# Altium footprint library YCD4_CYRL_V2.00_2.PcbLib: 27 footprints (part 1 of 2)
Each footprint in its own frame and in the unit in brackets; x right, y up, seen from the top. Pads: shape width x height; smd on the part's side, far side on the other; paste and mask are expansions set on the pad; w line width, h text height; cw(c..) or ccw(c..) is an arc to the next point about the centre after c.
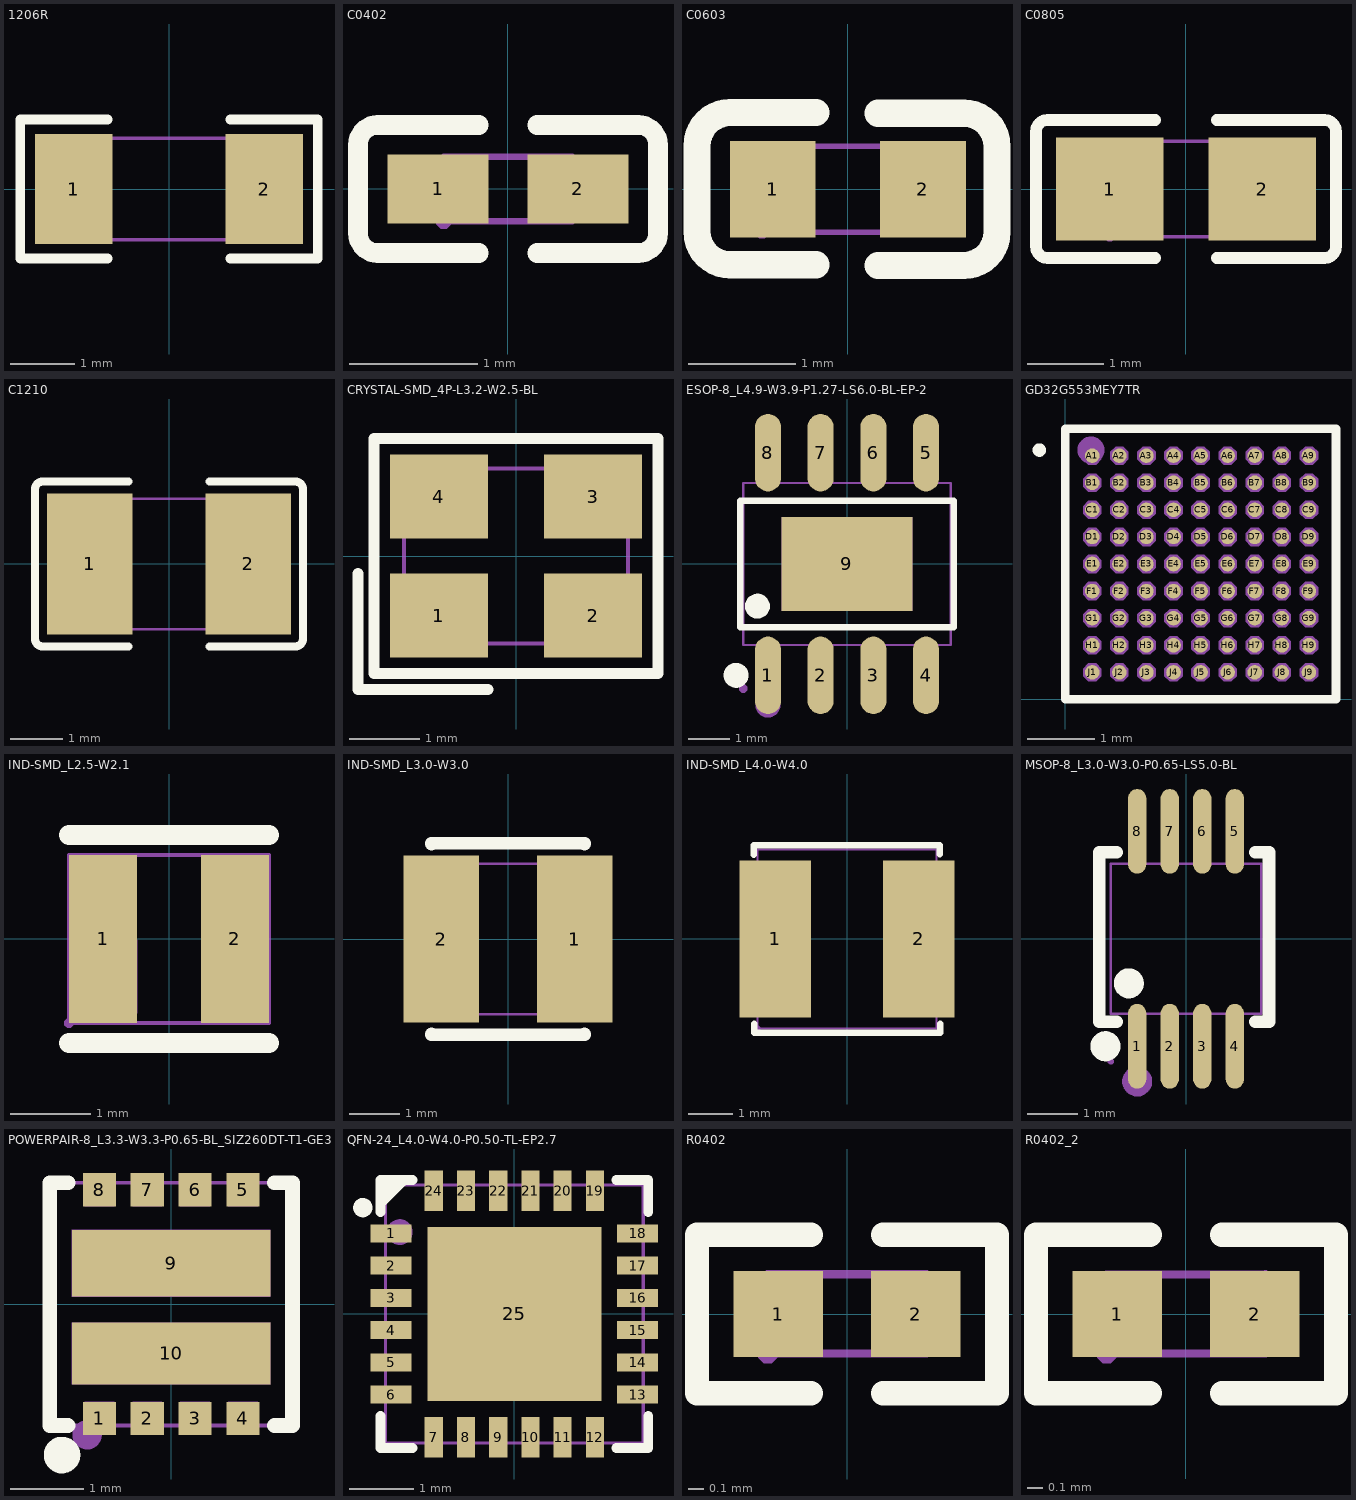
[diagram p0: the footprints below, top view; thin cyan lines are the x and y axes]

## 1206R [mm]
pads (2):
  rect 1.208x1.701 smd paste-100 mask+0.051: 1(-1.479,0) 2(1.479,0)
Top Overlay:
  lines w0.152: -0.951,-1.079 -2.311,-1.079 -2.311,1.079 -0.951,1.079 ; 0.951,-1.079 2.311,-1.079 2.311,1.079 0.951,1.079
Top Paste:
  region: -0.875,-0.75 -0.875,-0.389 -0.975,-0.289 -1.186,-0.289 -1.286,-0.189 -1.286,0.189 -1.186,0.289 -0.975,0.289 -0.875,0.389 -0.875,0.75 -0.975,0.85 -1.983,0.85 -2.083,0.75 -2.083,-0.75 -1.983,-0.85 -0.975,-0.85
  region: 0.875,-0.75 0.875,-0.389 0.975,-0.289 1.186,-0.289 1.286,-0.189 1.286,0.189 1.186,0.289 0.975,0.289 0.875,0.389 0.875,0.75 0.975,0.85 1.983,0.85 2.083,0.75 2.083,-0.75 1.983,-0.85 0.975,-0.85
Mechanical 15:
  region: 1.55,-0.788 1.55,0.788 1.1,0.788 1.1,-0.788
  region: -1.55,-0.788 -1.55,0.788 -1.1,0.788 -1.1,-0.788
  region: -1.49,-0.787 -1.49,-0.763 -1.525,-0.727 -1.575,-0.727 -1.61,-0.763 -1.61,-0.787 -1.61,-0.812 -1.575,-0.847 -1.525,-0.847 -1.49,-0.812 -1.49,-0.787
  lines w0.051: -1.55,-0.788 1.55,-0.788 1.55,0.788 -1.55,0.788 -1.55,-0.788
3D body: height 0.6, standoff 0, extent -1.479,-0.8 1.821,0.8

## C0402 [mm]
pads (2):
  rect 0.79x0.54 smd paste-100 mask+0.051: 1(-0.545,0) 2(0.545,0)
Top Overlay:
  lines w0.152: -0.226,-0.499 -1.016,-0.499 cw(c-1.016,-0.346) -1.169,-0.346 -1.169,0.346 cw(c-1.016,0.346) -1.016,0.499 -0.226,0.499 ; 0.226,-0.499 1.016,-0.499 ccw(c1.016,-0.346) 1.169,-0.346 1.169,0.346 ccw(c1.016,0.346) 1.016,0.499 0.226,0.499
Top Paste:
  region: -0.18,0.225 -0.18,-0.225 -0.25,-0.275 -0.73,-0.275 -0.78,-0.225 -0.78,0.225 -0.73,0.275 -0.25,0.275
  region: 0.78,0.225 0.78,-0.225 0.73,-0.275 0.25,-0.275 0.18,-0.225 0.18,0.225 0.25,0.275 0.73,0.275
Mechanical 15:
  region: -0.5,-0.25 -0.5,0.25 -0.25,0.25 -0.25,-0.25
  region: 0.5,-0.25 0.5,0.25 0.25,0.25 0.25,-0.25
  region: -0.44,-0.25 -0.44,-0.226 -0.475,-0.191 -0.524,-0.191 -0.559,-0.225 -0.56,-0.25 -0.559,-0.274 -0.525,-0.309 -0.476,-0.309 -0.441,-0.275 -0.44,-0.25
  lines w0.051: -0.5,-0.25 -0.5,0.25 0.5,0.25 0.5,-0.25 -0.5,-0.25
3D body: height 0.6, standoff 0, extent -0.731,-0.274 0.731,0.278

## C0603 [mm]
pads (2):
  rect 0.8x0.9 smd mask+0.102: 1(-0.7,0) 2(0.7,0)
Top Overlay:
  lines w0.254: -0.296,-0.704 -1.096,-0.704 cw(c-1.096,-0.394) -1.406,-0.394 -1.405,0.406 cw(c-1.096,0.406) -1.096,0.715 -0.296,0.715 ; 0.28,-0.71 1.08,-0.71 ccw(c1.08,-0.4) 1.39,-0.4 1.39,0.4 ccw(c1.08,0.4) 1.08,0.71 0.28,0.71
Mechanical 15:
  region: -0.8,-0.4 -0.8,0.4 -0.5,0.4 -0.5,-0.4
  region: 0.8,-0.4 0.8,0.4 0.5,0.4 0.5,-0.4
  region: -0.74,-0.4 -0.741,-0.376 -0.776,-0.343 -0.824,-0.343 -0.859,-0.376 -0.86,-0.4 -0.859,-0.424 -0.824,-0.458 -0.776,-0.458 -0.741,-0.424 -0.74,-0.4
  lines w0.051: -0.8,-0.4 -0.8,0.4 0.8,0.4 0.8,-0.4 -0.8,-0.4
3D body: height 1, standoff 0, extent -0.8,-0.4 1,0.4

## C0805 [mm]
pads (2):
  rect 1.41x1.35 smd paste-100 mask+0.051: 1(-1,0) 2(1,0)
Top Overlay:
  lines w0.152: -1.811,0.904 -0.401,0.904 ; -1.811,0.904 ccw(c-1.811,0.751) -1.964,0.751 -1.964,-0.751 ccw(c-1.811,-0.751) -1.811,-0.904 -0.401,-0.904 ; 0.401,-0.904 1.811,-0.904 ; 0.401,0.904 1.811,0.904 cw(c1.811,0.751) 1.964,0.751 ; 1.811,-0.904 ccw(c1.811,-0.751) 1.964,-0.751 1.964,0.751
Top Paste:
  region: 1.705,0.64 1.705,-0.64 1.655,-0.69 0.505,-0.69 0.455,-0.64 0.45,-0.23 0.9,-0.23 0.9,0.22 0.46,0.22 0.455,0.64 0.505,0.69 1.655,0.69
  region: -1.705,-0.64 -1.705,0.64 -1.655,0.69 -0.505,0.69 -0.455,0.64 -0.45,0.23 -0.9,0.23 -0.9,-0.22 -0.46,-0.22 -0.455,-0.64 -0.505,-0.69 -1.655,-0.69
Mechanical 15:
  region: 1,0.625 1,-0.625 0.5,-0.625 0.5,0.625
  region: -1,-0.625 -1,0.625 -0.5,0.625 -0.5,-0.625
  region: -0.94,-0.625 -0.94,-0.6 -0.975,-0.565 -1.025,-0.565 -1.06,-0.6 -1.06,-0.625 -1.06,-0.65 -1.025,-0.685 -0.975,-0.685 -0.94,-0.65 -0.94,-0.625
  lines w0.051: -1,-0.625 1,-0.625 1,0.625 -1,0.625 -1,-0.625
3D body: height 1.4, standoff 0, extent -1.097,-0.625 1.103,0.625

## C1210 [mm]
pads (2):
  rect 1.635x2.7 smd paste-100 mask+0.051: 1(-1.517,0) 2(1.517,0)
Top Overlay:
  lines w0.152: -0.776,-1.579 -2.411,-1.579 cw(c-2.411,-1.426) -2.564,-1.426 -2.564,1.426 cw(c-2.411,1.426) -2.411,1.579 -0.776,1.579 ; 0.776,-1.579 2.411,-1.579 ccw(c2.411,-1.426) 2.564,-1.426 2.564,1.426 ccw(c2.411,1.426) 2.411,1.579 0.776,1.579
Top Paste:
  region: 0.7,-1.25 0.7,-0.559 0.8,-0.459 1.156,-0.459 1.256,-0.359 1.256,0.359 1.156,0.459 0.8,0.459 0.7,0.559 0.7,1.25 0.8,1.35 2.235,1.35 2.335,1.25 2.335,-1.25 2.235,-1.35 0.8,-1.35
  region: -0.7,-1.25 -0.7,-0.559 -0.8,-0.459 -1.156,-0.459 -1.256,-0.359 -1.256,0.359 -1.156,0.459 -0.8,0.459 -0.7,0.559 -0.7,1.25 -0.8,1.35 -2.235,1.35 -2.335,1.25 -2.335,-1.25 -2.235,-1.35 -0.8,-1.35
Mechanical 15:
  region: -1.54,-1.25 -1.541,-1.226 -1.576,-1.193 -1.624,-1.193 -1.659,-1.226 -1.66,-1.25 -1.659,-1.274 -1.624,-1.307 -1.576,-1.307 -1.541,-1.274 -1.54,-1.25
  region: -1.6,-1.25 -1.6,1.25 -1,1.25 -1,-1.25
  region: 1.6,-1.25 1.6,1.25 1,1.25 1,-1.25
  lines w0.051: -1.6,-1.25 -1.6,1.25 1.6,1.25 1.6,-1.25 -1.6,-1.25
3D body: height 2.8, standoff 0, extent -1.403,-1.25 1.797,1.25

## CRYSTAL-SMD_4P-L3.2-W2.5-BL [mm]
pads (4):
  rect 1.4x1.2 smd: 1(-1.1,-0.85) 2(1.1,-0.85) 3(1.1,0.85) 4(-1.1,0.85)
Top Overlay:
  lines w0.152: -2.257,-0.25 -2.257,-1.907 -0.4,-1.907 ; -2.029,-1.678 -2.029,1.679 2.029,1.679 2.029,-1.678 -2.029,-1.678
Mechanical 6:
  circle w0.36: c-1.143,-0.889 r0.18
Mechanical 15:
  region: -1.54,-1.25 -1.54,-1.225 -1.575,-1.19 -1.625,-1.19 -1.66,-1.225 -1.66,-1.25 -1.66,-1.275 -1.625,-1.31 -1.575,-1.31 -1.54,-1.275 -1.54,-1.25
  region: -1.5,1.15 -0.6,1.15 -0.6,0.35 -1.5,0.35
  region: 0.6,1.15 1.5,1.15 1.5,0.35 0.6,0.35
  region: 0.6,-0.35 1.5,-0.35 1.5,-1.15 0.6,-1.15
  region: -1.5,-0.35 -0.6,-0.35 -0.6,-1.15 -1.5,-1.15
  lines w0.051: -1.6,-1.25 -1.6,1.25 1.6,1.25 1.6,-1.25 -1.6,-1.25
3D body: height 0.8, standoff 0, extent -1.6,-1.25 1.6,1.25

## ESOP-8_L4.9-W3.9-P1.27-LS6.0-BL-EP-2 [mm]
pads (9):
  oval 0.63x1.865 smd: 1(-1.905,-2.683) 2(-0.635,-2.683) 3(0.635,-2.683) 4(1.905,-2.683) 5(1.905,2.682) 6(0.635,2.682) 7(-0.635,2.682) 8(-1.905,2.682)
  rect 3.15x2.26 smd paste+0 mask+0.05: 9(0,0)
Top Overlay:
  circle w0.3: c-2.672,-2.683 r0.15
  circle w0.3: c-2.159,-1.016 r0.15
  lines w0.152: -2.576,-1.521 2.576,-1.521 2.576,1.521 -2.576,1.521 -2.576,-1.521
Mechanical 6:
  circle w0.3: c-1.905,-3.4 r0.15
Mechanical 15:
  region: -1.575,1.13 1.575,1.13 1.575,-1.13 -1.575,-1.13
  region: -2.115,-3 -2.115,-2.165 -1.695,-2.165 -1.695,-3
  region: -2.115,-2.175 -2.115,-1.94 -1.695,-1.94 -1.695,-2.175
  region: -0.845,-3 -0.845,-2.165 -0.425,-2.165 -0.425,-3
  region: -0.845,-2.175 -0.845,-1.94 -0.425,-1.94 -0.425,-2.175
  region: 0.425,-3 0.425,-2.165 0.845,-2.165 0.845,-3
  region: 0.425,-2.175 0.425,-1.94 0.845,-1.94 0.845,-2.175
  region: 1.695,-3 1.695,-2.165 2.115,-2.165 2.115,-3
  region: 1.695,-2.175 1.695,-1.94 2.115,-1.94 2.115,-2.175
  region: -2.115,2.165 -2.115,3 -1.695,3 -1.695,2.165
  region: -2.115,1.94 -2.115,2.175 -1.695,2.175 -1.695,1.94
  region: -0.845,2.165 -0.845,3 -0.425,3 -0.425,2.165
  region: -0.845,1.94 -0.845,2.175 -0.425,2.175 -0.425,1.94
  region: 0.425,2.165 0.425,3 0.845,3 0.845,2.165
  region: 0.425,1.94 0.425,2.175 0.845,2.175 0.845,1.94
  region: 1.695,2.165 1.695,3 2.115,3 2.115,2.165
  region: 1.695,1.94 1.695,2.175 2.115,2.175 2.115,1.94
  region: -2.4,-3 -2.4,-2.959 -2.459,-2.9 -2.541,-2.9 -2.6,-2.959 -2.6,-3 -2.6,-3.042 -2.541,-3.1 -2.458,-3.1 -2.4,-3.041 -2.4,-3
  lines w0.051: -2.5,-1.95 2.5,-1.95 2.5,1.95 -2.5,1.95 -2.5,-1.95
3D body: height 1.7, standoff 0, extent -2.505,-1.943 2.489,1.943

## GD32G553MEY7TR [mm]
pads (81):
  round 0.216 smd paste-100 mask+0.051: A1(0.4,3.6) A2(0.8,3.6) A3(1.2,3.6) A4(1.6,3.6) A5(2,3.6) A6(2.4,3.6) A7(2.8,3.6) A8(3.2,3.6) A9(3.6,3.6) B1(0.4,3.2) B2(0.8,3.2) B3(1.2,3.2) B4(1.6,3.2) B5(2,3.2) B6(2.4,3.2) B7(2.8,3.2) B8(3.2,3.2) B9(3.6,3.2) C1(0.4,2.8) C2(0.8,2.8) C3(1.2,2.8) C4(1.6,2.8) C5(2,2.8) C6(2.4,2.8) C7(2.8,2.8) C8(3.2,2.8) C9(3.6,2.8) D1(0.4,2.4) D2(0.8,2.4) D3(1.2,2.4) D4(1.6,2.4) D5(2,2.4) D6(2.4,2.4) D7(2.8,2.4) D8(3.2,2.4) D9(3.6,2.4) E1(0.4,2) E2(0.8,2) E3(1.2,2) E4(1.6,2) E5(2,2) E6(2.4,2) E7(2.8,2) E8(3.2,2) E9(3.6,2) F1(0.4,1.6) F2(0.8,1.6) F3(1.2,1.6) F4(1.6,1.6) F5(2,1.6) F6(2.4,1.6) F7(2.8,1.6) F8(3.2,1.6) F9(3.6,1.6) G1(0.4,1.2) G2(0.8,1.2) G3(1.2,1.2) G4(1.6,1.2) G5(2,1.2) G6(2.4,1.2) G7(2.8,1.2) G8(3.2,1.2) G9(3.6,1.2) H1(0.4,0.8) H2(0.8,0.8) H3(1.2,0.8) H4(1.6,0.8) H5(2,0.8) H6(2.4,0.8) H7(2.8,0.8) H8(3.2,0.8) H9(3.6,0.8) J1(0.4,0.4) J2(0.8,0.4) J3(1.2,0.4) J4(1.6,0.4) J5(2,0.4) J6(2.4,0.4) J7(2.8,0.4) J8(3.2,0.4) J9(3.6,0.4)
Top Overlay:
  circle w0.1: c-0.381,3.683 r0.05
  lines w0.127: 0,0 0,4 4,4 4,0 0,0
Top Paste:
  drawing of 81 lines, arcs and shapes, not listed
Mechanical 6:
  circle w0.2: c0.381,3.683 r0.1
Mechanical 15:
  drawing of 81 lines, arcs and shapes, not listed

## IND-SMD_L2.5-W2.1 [mm]
pads (2):
  rect 0.85x2.1 smd: 1(-0.825,0) 2(0.825,0)
Top Overlay:
  lines w0.254: -1.25,-1.3 1.25,-1.3 ; -1.25,1.3 1.25,1.3
Mechanical 15:
  region: 1.25,0.925 1.25,-0.925 0.4,-0.925 0.4,0.925
  region: -0.4,0.925 -0.4,-0.925 -1.25,-0.925 -1.25,0.925
  region: -1.19,-1.05 -1.19,-1.025 -1.225,-0.99 -1.275,-0.99 -1.31,-1.025 -1.31,-1.05 -1.31,-1.075 -1.275,-1.11 -1.225,-1.11 -1.19,-1.075 -1.19,-1.05
  lines w0.051: -1.25,-1.05 1.25,-1.05 1.25,1.05 -1.25,1.05 -1.25,-1.05
3D body: height 1.25, standoff 0, extent -1.25,-1.05 1.25,1.05

## IND-SMD_L3.0-W3.0 [mm]
pads (2):
  rect 1.5x3.32 smd: 1(1.328,0) 2(-1.328,0)
Top Overlay:
  lines w0.254: -1.524,-1.891 -1.524,-1.905 1.524,-1.905 1.524,-1.891 ; -1.524,1.891 -1.524,1.905 1.524,1.905 1.524,1.891
Mechanical 15:
  region: -1.5,-1.45 -1.5,1.45 -0.75,1.45 -0.75,-1.45
  region: 1.5,-1.45 1.5,1.45 0.75,1.45 0.75,-1.45
  region: -1.44,-1.5 -1.44,-1.475 -1.475,-1.44 -1.525,-1.44 -1.56,-1.475 -1.56,-1.5 -1.56,-1.525 -1.525,-1.56 -1.475,-1.56 -1.44,-1.525 -1.44,-1.5
  lines w0.051: -1.5,-1.5 -1.5,1.5 1.5,1.5 1.5,-1.5 -1.5,-1.5
3D body: height 1.5, standoff 0, extent -1.5,-1.5 1.5,1.5

## IND-SMD_L4.0-W4.0 [mm]
pads (2):
  rect 1.6x3.5 smd: 1(-1.6,0) 2(1.6,0)
Top Overlay:
  lines w0.15: -2.08,1.88 -2.083,2.095 2.07,2.095 2.07,1.9 ; -2.07,-1.89 -2.07,-2.096 2.082,-2.096 2.08,-1.9
Mechanical 15:
  region: -2,1.65 -1.05,1.65 -1.05,-1.65 -2,-1.65
  region: 1.05,1.65 2,1.65 2,-1.65 1.05,-1.65
  region: -1.94,-2 -1.941,-1.976 -1.976,-1.943 -2.024,-1.943 -2.059,-1.976 -2.06,-2 -2.059,-2.024 -2.024,-2.057 -1.976,-2.057 -1.941,-2.024
  lines w0.051: -2,-2 2,-2 2,2 -2,2 -2,-2
3D body: height 1.8, standoff 0, extent -2,-2 2,2

## MSOP-8_L3.0-W3.0-P0.65-LS5.0-BL [mm]
pads (8):
  oval 0.364x1.692 smd: 1(-0.975,-2.146) 2(-0.325,-2.146) 3(0.325,-2.146) 4(0.975,-2.146) 5(0.975,2.146) 6(0.325,2.146) 7(-0.325,2.146) 8(-0.975,2.146)
Top Overlay:
  circle w0.3: c-1.609,-2.146 r0.15
  circle w0.3: c-1.143,-0.889 r0.15
  lines w0.254: -1.73,1.724 -1.73,-1.652 -1.723,-1.658 -1.388,-1.658 ; -1.717,1.71 -1.697,1.73 -1.388,1.73 ; 1.388,-1.658 1.659,-1.658 1.659,1.73 1.388,1.73
Mechanical 6:
  circle w0.3: c-0.975,-2.85 r0.15
Mechanical 15:
  region: 0.82,1.86 0.82,1.49 1.13,1.49 1.13,1.86
  region: 0.82,2.45 0.82,1.85 1.13,1.85 1.13,2.45
  region: 0.17,1.86 0.17,1.49 0.48,1.49 0.48,1.86
  region: 0.17,2.45 0.17,1.85 0.48,1.85 0.48,2.45
  region: -0.48,1.86 -0.48,1.49 -0.17,1.49 -0.17,1.86
  region: -0.48,2.45 -0.48,1.85 -0.17,1.85 -0.17,2.45
  region: -1.13,1.86 -1.13,1.49 -0.82,1.49 -0.82,1.86
  region: -1.13,2.45 -1.13,1.85 -0.82,1.85 -0.82,2.45
  region: 0.82,-1.86 0.82,-1.49 1.13,-1.49 1.13,-1.86
  region: 0.82,-2.45 0.82,-1.85 1.13,-1.85 1.13,-2.45
  region: 0.17,-1.86 0.17,-1.49 0.48,-1.49 0.48,-1.86
  region: 0.17,-2.45 0.17,-1.85 0.48,-1.85 0.48,-2.45
  region: -0.48,-1.86 -0.48,-1.49 -0.17,-1.49 -0.17,-1.86
  region: -0.48,-2.45 -0.48,-1.85 -0.17,-1.85 -0.17,-2.45
  region: -1.13,-1.86 -1.13,-1.49 -0.82,-1.49 -0.82,-1.86
  region: -1.13,-2.45 -1.13,-1.85 -0.82,-1.85 -0.82,-2.45
  region: -1.44,-2.45 -1.44,-2.425 -1.475,-2.39 -1.525,-2.39 -1.56,-2.425 -1.56,-2.45 -1.56,-2.475 -1.525,-2.51 -1.475,-2.51 -1.44,-2.475 -1.44,-2.45
  lines w0.051: -1.5,-1.5 1.5,-1.5 1.5,1.5 -1.5,1.5 -1.5,-1.5
3D body: height 1.7, standoff 0, extent -1.524,-1.524 1.524,1.524

## POWERPAIR-8_L3.3-W3.3-P0.65-BL_SIZ260DT-T1-GE3 [mm]
pads (10):
  rect 0.45x0.45 smd paste+0 mask+0.05: 1(-0.975,-1.555) 2(-0.325,-1.555) 3(0.325,-1.555) 4(0.975,-1.555) 5(0.975,1.555) 6(0.325,1.555) 7(-0.325,1.555) 8(-0.975,1.555)
  rect 2.7x0.91 smd paste+0 mask+0.05: 9(0,0.555)
  rect 2.7x0.84 smd paste+0 mask+0.05: 10(0,-0.671)
Top Overlay:
  circle w0.254: c-1.485,-2.053 r0.122
  lines w0.2: -1.404,-1.651 -1.651,-1.651 -1.651,1.651 -1.404,1.651 ; 1.404,-1.651 1.651,-1.651 1.651,1.651 1.404,1.651
Mechanical 6:
  circle w0.2: c-1.143,-1.778 r0.1
Mechanical 15:
  region: -1.59,-1.65 -1.591,-1.626 -1.626,-1.593 -1.674,-1.593 -1.709,-1.626 -1.71,-1.65 -1.709,-1.674 -1.674,-1.707 -1.626,-1.707 -1.591,-1.674 -1.59,-1.65
  region: -1.175,1.65 -0.775,1.65 -0.775,1.33 -1.175,1.33
  region: -0.525,1.65 -0.125,1.65 -0.125,1.33 -0.525,1.33
  region: 0.125,1.65 0.525,1.65 0.525,1.33 0.125,1.33
  region: 0.775,1.65 1.175,1.65 1.175,1.33 0.775,1.33
  region: 0.775,-1.33 1.175,-1.33 1.175,-1.65 0.775,-1.65
  region: 0.125,-1.33 0.525,-1.33 0.525,-1.65 0.125,-1.65
  region: -0.525,-1.33 -0.125,-1.33 -0.125,-1.65 -0.525,-1.65
  region: -1.175,-1.33 -0.775,-1.33 -0.775,-1.65 -1.175,-1.65
  region: -1.35,1.01 1.35,1.01 1.35,0.1 -1.35,0.1
  region: -1.35,-0.251 1.35,-0.251 1.35,-1.091 -1.35,-1.091
  lines w0.051: -1.65,-1.65 -1.65,1.65 1.65,1.65 1.65,-1.65 -1.65,-1.65
3D body: height 0.8, standoff 0, extent -1.651,-1.651 1.651,1.651

## QFN-24_L4.0-W4.0-P0.50-TL-EP2.7 [mm]
pads (25):
  rect 0.633x0.28 smd paste-100 mask+0.051: 1(-1.912,1.25) 2(-1.912,0.75) 3(-1.912,0.25) 4(-1.912,-0.25) 5(-1.912,-0.75) 6(-1.912,-1.25) 13(1.912,-1.25) 14(1.912,-0.75) 15(1.912,-0.25) 16(1.912,0.25) 17(1.912,0.75) 18(1.912,1.25)
  rect 0.28x0.633 smd paste-100 mask+0.051: 7(-1.25,-1.912) 8(-0.75,-1.912) 9(-0.25,-1.912) 10(0.25,-1.912) 11(0.75,-1.912) 12(1.25,-1.912) 19(1.25,1.912) 20(0.75,1.912) 21(0.25,1.912) 22(-0.25,1.912) 23(-0.75,1.912) 24(-1.25,1.912)
  rect 2.7x2.7 smd paste-100 mask+0.051: 25(0,0)
Top Overlay:
  circle w0.15: c-2.35,1.65 r0.075
  region: -1.58,2.076 -2.076,2.076 -2.076,1.7
  lines w0.152: -2.076,-1.58 -2.076,-2.076 -1.58,-2.076 ; -2.076,1.58 -2.076,2.076 -1.58,2.076 -1.713,2.076 -2.076,1.713 ; 1.58,-2.076 2.076,-2.076 2.076,-1.58 ; 1.58,2.076 2.076,2.076 2.076,1.58
Top Paste:
  region: -1.08,1.08 1.08,1.08 1.08,-1.08 -1.08,-1.08
  region: -2.228,1.39 -1.595,1.39 -1.595,1.11 -2.228,1.11
  region: -2.228,0.89 -1.595,0.89 -1.595,0.61 -2.228,0.61
  region: -2.228,0.39 -1.595,0.39 -1.595,0.11 -2.228,0.11
  region: -2.228,-0.11 -1.595,-0.11 -1.595,-0.39 -2.228,-0.39
  region: -2.228,-0.61 -1.595,-0.61 -1.595,-0.89 -2.228,-0.89
  region: -2.228,-1.11 -1.595,-1.11 -1.595,-1.39 -2.228,-1.39
  region: -1.39,-1.595 -1.11,-1.595 -1.11,-2.228 -1.39,-2.228
  region: -0.89,-1.595 -0.61,-1.595 -0.61,-2.228 -0.89,-2.228
  region: -0.39,-1.595 -0.11,-1.595 -0.11,-2.228 -0.39,-2.228
  region: 0.11,-1.595 0.39,-1.595 0.39,-2.228 0.11,-2.228
  region: 0.61,-1.595 0.89,-1.595 0.89,-2.228 0.61,-2.228
  region: 1.11,-1.595 1.39,-1.595 1.39,-2.228 1.11,-2.228
  region: 1.595,-1.11 2.228,-1.11 2.228,-1.39 1.595,-1.39
  region: 1.595,-0.61 2.228,-0.61 2.228,-0.89 1.595,-0.89
  region: 1.595,-0.11 2.228,-0.11 2.228,-0.39 1.595,-0.39
  region: 1.595,0.39 2.228,0.39 2.228,0.11 1.595,0.11
  region: 1.595,0.89 2.228,0.89 2.228,0.61 1.595,0.61
  region: 1.595,1.39 2.228,1.39 2.228,1.11 1.595,1.11
  region: 1.11,2.228 1.39,2.228 1.39,1.595 1.11,1.595
  region: 0.61,2.228 0.89,2.228 0.89,1.595 0.61,1.595
  region: 0.11,2.228 0.39,2.228 0.39,1.595 0.11,1.595
  region: -0.39,2.228 -0.11,2.228 -0.11,1.595 -0.39,1.595
  region: -0.89,2.228 -0.61,2.228 -0.61,1.595 -0.89,1.595
  region: -1.39,2.228 -1.11,2.228 -1.11,1.595 -1.39,1.595
Mechanical 6:
  circle w0.2: c-1.778,1.27 r0.1
Mechanical 15:
  region: -1.94,2 -1.941,2.024 -1.976,2.059 -2.024,2.059 -2.059,2.024 -2.06,2 -2.059,1.975 -2.024,1.941 -1.975,1.941 -1.941,1.976 -1.94,2
  region: -2,1.37 -1.62,1.37 -1.62,1.13 -2,1.13
  region: -2,0.87 -1.62,0.87 -1.62,0.63 -2,0.63
  region: -2,0.37 -1.62,0.37 -1.62,0.13 -2,0.13
  region: -2,-0.13 -1.62,-0.13 -1.62,-0.37 -2,-0.37
  region: -2,-0.63 -1.62,-0.63 -1.62,-0.87 -2,-0.87
  region: -2,-1.13 -1.62,-1.13 -1.62,-1.37 -2,-1.37
  region: -1.37,-1.62 -1.13,-1.62 -1.13,-2 -1.37,-2
  region: -0.87,-1.62 -0.63,-1.62 -0.63,-2 -0.87,-2
  region: -0.37,-1.62 -0.13,-1.62 -0.13,-2 -0.37,-2
  region: 0.13,-1.62 0.37,-1.62 0.37,-2 0.13,-2
  region: 0.63,-1.62 0.87,-1.62 0.87,-2 0.63,-2
  region: 1.13,-1.62 1.37,-1.62 1.37,-2 1.13,-2
  region: 2,-1.13 1.62,-1.13 1.62,-1.37 2,-1.37
  region: 2,-0.63 1.62,-0.63 1.62,-0.87 2,-0.87
  region: 2,-0.13 1.62,-0.13 1.62,-0.37 2,-0.37
  region: 2,0.37 1.62,0.37 1.62,0.13 2,0.13
  region: 2,0.87 1.62,0.87 1.62,0.63 2,0.63
  region: 2,1.37 1.62,1.37 1.62,1.13 2,1.13
  region: 1.13,1.62 1.37,1.62 1.37,2 1.13,2
  region: 0.63,1.62 0.87,1.62 0.87,2 0.63,2
  region: 0.13,1.62 0.37,1.62 0.37,2 0.13,2
  region: -0.37,1.62 -0.13,1.62 -0.13,2 -0.37,2
  region: -0.87,1.62 -0.63,1.62 -0.63,2 -0.87,2
  region: -1.37,1.62 -1.13,1.62 -1.13,2 -1.37,2
  region: -1,1.25 1.25,1.25 1.25,-1.25 -1.25,-1.25 -1.25,1
  lines w0.051: -2,-2 2,-2 2,2 -2,2 -2,-2
3D body: height 0.9, standoff 0, extent -2.007,-2.018 2.032,2.039

## R0402 [mm]
pads (2):
  rect 0.566x0.54 smd paste-100 mask+0.051: 1(-0.433,0) 2(0.433,0)
Top Overlay:
  lines w0.152: -0.226,-0.499 -0.944,-0.499 -0.944,0.499 -0.226,0.499 ; 0.226,-0.499 0.944,-0.499 0.944,0.499 0.226,0.499
Top Paste:
  region: 0.135,-0.23 0.135,0.23 0.175,0.27 0.676,0.27 0.716,0.23 0.716,-0.23 0.676,-0.27 0.175,-0.27
  region: -0.135,-0.23 -0.135,0.23 -0.175,0.27 -0.676,0.27 -0.716,0.23 -0.716,-0.23 -0.676,-0.27 -0.175,-0.27
Mechanical 15:
  region: 0.251,-0.25 0.251,0.25 0.501,0.25 0.501,-0.25
  region: -0.249,0.25 -0.249,-0.25 -0.499,-0.25 -0.499,0.25
  region: -0.44,-0.25 -0.44,-0.225 -0.475,-0.19 -0.525,-0.19 -0.56,-0.225 -0.56,-0.25 -0.56,-0.275 -0.525,-0.31 -0.475,-0.31 -0.44,-0.275 -0.44,-0.25
  lines w0.051: -0.5,-0.25 -0.5,0.25 0.5,0.25 0.5,-0.25 -0.5,-0.25
3D body: height 0.6, standoff 0, extent -0.5,-0.25 0.501,0.25

## R0402_2 [mm]
pads (2):
  rect 0.566x0.54 smd paste-100 mask+0.051: 1(-0.433,0) 2(0.433,0)
Top Overlay:
  lines w0.152: -0.226,-0.499 -0.944,-0.499 -0.944,0.499 -0.226,0.499 ; 0.226,-0.499 0.944,-0.499 0.944,0.499 0.226,0.499
Top Paste:
  region: 0.135,-0.23 0.135,0.23 0.175,0.27 0.676,0.27 0.716,0.23 0.716,-0.23 0.676,-0.27 0.175,-0.27
  region: -0.135,-0.23 -0.135,0.23 -0.175,0.27 -0.676,0.27 -0.716,0.23 -0.716,-0.23 -0.676,-0.27 -0.175,-0.27
Mechanical 15:
  region: 0.251,-0.25 0.251,0.25 0.501,0.25 0.501,-0.25
  region: -0.249,0.25 -0.249,-0.25 -0.499,-0.25 -0.499,0.25
  region: -0.44,-0.25 -0.44,-0.225 -0.475,-0.19 -0.525,-0.19 -0.56,-0.225 -0.56,-0.25 -0.56,-0.275 -0.525,-0.31 -0.475,-0.31 -0.44,-0.275 -0.44,-0.25
  lines w0.051: -0.5,-0.25 -0.5,0.25 0.5,0.25 0.5,-0.25 -0.5,-0.25
3D body: height 0.6, standoff 0, extent -0.5,-0.25 0.501,0.25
